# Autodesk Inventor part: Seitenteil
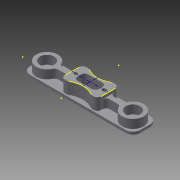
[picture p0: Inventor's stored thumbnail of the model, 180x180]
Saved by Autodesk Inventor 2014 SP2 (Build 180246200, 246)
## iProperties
Created: 2015-04
Part Number: Seitenteil
Material: Generisch
Document SubType Name: Modeling
Designer: e_krauts
Density: 1 g/cm^3
Appearance: Vorgabe
Mass: 43.9559 g
Surface Area: 202.761 cm^2
Volume: 43.9559 cm^3
Author: e_krauts
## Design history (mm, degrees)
sketch "Skizze1"
  geometry: L1 (0, 0)-(154, 0); L2 (154, 0)-(154, 34); L3 (154, 34)-(0, 34); L4 (0, 34)-(0, 0)
  constraints: 8 end point, 2 parallel, 1 horizontal, 1 perpendicular
  dimensions: "d0" = 154 distance of L3.end L2.end; "d1" = 34 distance between parallel lines of L3 L1
extrude "Extrusion1" new body sketch "Skizze1" distance "d2" = 3.5; taper "d3" = 0 deg
sketch "Skizze2"
  geometry: L1 (0, 0)-(154, 0) reference; L2 (154, 0)-(154, 34) reference; L3 (154, 34)-(0, 34) reference; L4 (0, 34)-(0, 0) reference; L5 (77, 34)-(77, 0); L6 (0, 17)-(154, 17); L7 (77, 20)-(35.33, 20); L8 (77, 14)-(35.33, 14); L9 (77, 20)-(118.67, 20); L10 (77, 14)-(118.67, 14); L11 (154, 17)-(0, 17); A1 r 5 centre (35.33, 25) between (30.748, 23) and (35.33, 20); A2 r 15 centre (17, 17) between (30.748, 23) and (2, 17); A3 r 5 centre (35.33, 9) between (35.33, 14) and (30.748, 11); A4 r 15 centre (17, 17) between (2, 17) and (30.748, 11); A5 r 5 centre (118.67, 25) between (118.67, 20) and (123.252, 23); A6 r 15 centre (137, 17) between (123.252, 11) and (152, 17); A7 r 15 centre (137, 17) between (152, 17) and (123.252, 23); A8 r 5 centre (118.67, 9) between (123.252, 11) and (118.67, 14)
  constraints: 16 point on circle, 14 end point, 14 symmetric about line, 8 centre point, 5 point on line, 4 midpoint, 2 tangent, 1 parallel, 6 other
  dimensions: "d4" = 6 diameter of L7 L6; "d5" = 15 radius of A2; "d6" = 120 diameter of A2.centre L5; "d7" = 5 radius of A1
extrude "Extrusion2" join sketch "Skizze2" distance "d8" = 12; taper "d9" = 0 deg
sketch "Skizze3"
  geometry: A1 r 15 centre (17, 17) between (30.748, 23) and (30.748, 11) reference; A2 r 15 centre (137, 17) between (123.252, 11) and (123.252, 23) reference; 3 further points
  constraints: 2 coincident
hole "Bohrung1" sketch "Skizze3" at (17, 17), (137, 17) diameter "d10" = 20; stored, may be unused: countersink angle "d14" = 90 deg, drill point angle "d16" = 0 deg; dims "d11" = 6, "d12" = 4, "d13" = 2, "d15" = 12
fillet "Rundung1" dims "d17" = 10
sketch "Skizze4"
  geometry: L1 (144, 34)-(10, 34) reference; L2 (0, 24)-(0, 10) reference; L3 (10, 0)-(144, 0) reference; L4 (154, 10)-(154, 24) reference; L5 (77, 34)-(77, 0); L6 (0, 17)-(154, 17); L7 (102.5, 32)-(51.5, 32); L8 (51.5, 32)-(51.5, 2); L9 (51.5, 2)-(102.5, 2); L10 (102.5, 2)-(102.5, 32); L11 (102.5, 32)-(51.5, 2); L12 (51.5, 32)-(102.5, 2); 2 further points
  constraints: 16 end point, 7 midpoint, 2 parallel, 1 horizontal, 1 perpendicular
  dimensions: "d18" = 51 distance of L9.end L8.end; "d19" = 30 distance of L8.end L7.end
extrude "Extrusion3" join sketch "Skizze4" distance "d20" = 16.5; taper "d21" = 0 deg
fillet "Rundung2" dims "d22" = 5
sketch "Skizze5"
  geometry: L1 (62, 24.5)-(92, 24.5); L2 (92, 24.5)-(92, 9.5); L3 (92, 9.5)-(62, 9.5); L4 (62, 9.5)-(62, 24.5); L5 (62, 24.5)-(92, 9.5); L6 (92, 24.5)-(62, 9.5); 2 further points
  constraints: 12 end point, 2 midpoint, 2 parallel, 1 horizontal, 1 perpendicular
  dimensions: "d23" = 30 distance of L2.end L3.end; "d24" = 15 distance of L1.end L2.end
extrude "Extrusion4" cut sketch "Skizze5" distance "d25" = 16.5; taper "d26" = 0 deg
fillet "Rundung3" dims "d27" = 5
sketch "Skizze6"
  geometry: L1 (51.5, 27)-(51.5, 7) reference; L2 (56.5, 2)-(97.5, 2) reference; L3 (102.5, 7)-(102.5, 27) reference; L4 (97.5, 32)-(56.5, 32) reference; L5 (51.5, 17)-(102.5, 17); L6 (77, 32)-(77, 2); L7 (60.417, 32)-(93.583, 32); L8 (60.417, 2)-(93.583, 2); A1 r 30 centre (77, 57) between (60.417, 32) and (93.583, 32); A2 r 30 centre (77, -23) between (93.583, 2) and (60.417, 2); 1 further point
  constraints: 8 end point, 4 midpoint, 4 point on circle, 3 symmetric about line, 2 centre point, 2 point on line, 1 collinear, 1 other
  dimensions: "d30" = 80 diameter of A1.centre L5; "d31" = 30 radius of A1
extrude "Extrusion5" cut sketch "Skizze6" distance "d32" = 16.5; taper "d33" = 0 deg
fillet "Rundung4" dims "d34" = 5
sketch "Skizze7"
  geometry: L1 (51.5, 27)-(51.5, 7) reference; L2 (102.5, 7)-(102.5, 27) reference; L3 (51.5, 17)-(102.5, 17); L4 (77, 27)-(77, 7); A1 r 30 centre (77, -23) between (92.452, 2.714) and (61.548, 2.714) reference; A2 r 30 centre (77, 57) between (61.548, 31.286) and (92.452, 31.286) reference; 3 further points
  constraints: 4 end point, 2 midpoint, 2 point on circle, 1 point on line, 1 symmetric about line
hole "Bohrung2" sketch "Skizze7" diameter "d36" = 4.134; stored, may be unused: countersink angle "d40" = 90 deg, drill point angle "d42" = 118 deg; dims "d37" = 14, "d38" = 4, "d39" = 2, "d41" = 17
sketch "Skizze9"
  geometry: C1 r 5.2 at (0, 0) reference; 2 further points
  constraints: 1 coincident
hole "Bohrung4" sketch "Skizze9" diameter "d61" = 5.5; stored, may be unused: countersink angle "d65" = 90 deg, drill point angle "d67" = 118 deg; dims "d62" = 6, "d63" = 10.4, "d64" = 2, "d66" = 8
node "Volumenkörper1"
hole "Bohrung3" diameter "d54" = 10.4; stored, may be unused: countersink angle "d58" = 90 deg, drill point angle "d60" = 0 deg; dims "d52" = 17, "d53" = 57, "d55" = 6, "d56" = 4, "d57" = 2, "d59" = 0.5
